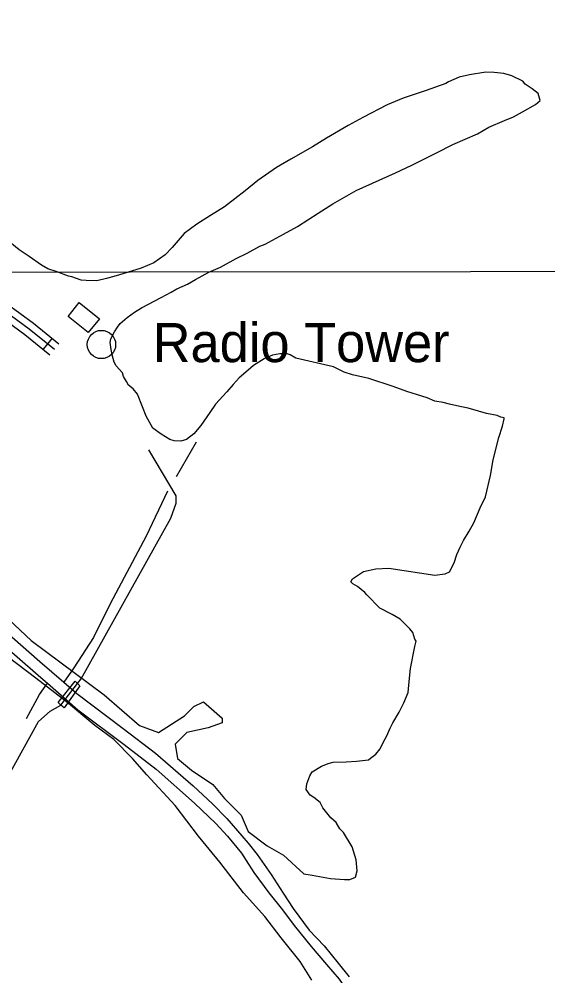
# Model space of a CAD drawing. Extents: x 3297735 to 3335592, y 670436 to 695807.
# Drawn here: x 3318525 to 3319645, y 677364 to 679392 of the extents above; entities that cross this region are included whole.
import ezdxf

# ---------------------------------------------------------------- set-up
doc = ezdxf.new("R2010")
doc.units = 0
for name, color, linetype in [('V-BLDG-OTLN', 7, 'Continuous'), ('V-BRDG-OTLN', 7, 'Continuous'), ('V-DTCH-CNTR', 7, 'Continuous'), ('V-GRID-MAJR', 7, 'Continuous'), ('V-ROAD-CNTR', 7, 'Continuous'), ('V-SITE-VEGE', 7, 'Continuous'), ('V-TOPO-SHOR', 7, 'Continuous'), ('V-TOPO-TOWR', 7, 'Continuous'), ('V-TOPO-TOWR-IDEN', 7, 'Continuous')]:
    doc.layers.add(name, color=color, linetype=linetype)

msp = doc.modelspace()

# ---------------------------------------------------------------- linework, layer by layer
at = {"layer": 'V-BLDG-OTLN'}
msp.add_lwpolyline([(3318652.3, 678791.7), (3318695, 678757.3), (3318671.4, 678728), (3318628.7, 678762.4)], close=True, dxfattribs=at)
at = {"layer": 'V-BRDG-OTLN'}
msp.add_lwpolyline([(3318607.4, 677943.8), (3318643.8, 677989.1), (3318648.7, 677984), (3318653.3, 677979.3), (3318620.4, 677932.6), (3318613.7, 677938.4)], close=True, dxfattribs=at)
at = {"layer": 'V-DTCH-CNTR'}
msp.add_lwpolyline([(3317457.5, 675830.8), (3317578.4, 676057.1), (3317642.4, 676178), (3317859.6, 676585.3), (3318115.7, 677073.2), (3318362.6, 677536.5), (3318566, 677903.4), (3318590.9, 677925.7), (3318613.7, 677938.4), (3318622.6, 677950.1), (3318648.7, 677984), (3318656.8, 677994.1), (3318846.3, 678334.9), (3318857.9, 678366.3), (3318858, 678382), (3318799.5, 678479.6)], dxfattribs=at)
at = {"layer": 'V-GRID-MAJR'}
msp.add_lwpolyline([(3301860.2, 678842.7), (3303311.9, 678843.6), (3306791, 678845.9), (3310174.4, 678848.5), (3313813, 678851.6), (3318760.4, 678856.5), (3322367.1, 678860.5), (3326388.7, 678865.3), (3330442.3, 678870.6), (3332389.2, 678873.4), (3333397.1, 678874.8)], dxfattribs=at)
at = {"layer": 'V-ROAD-CNTR'}
msp.add_line((3318595, 678715.9), (3318576.1, 678692.5), dxfattribs=at)
for points in [[(3317349.6, 679502), (3317551.8, 679371.6), (3317787.2, 679224.3), (3318042.2, 679069), (3318228, 678955.6), (3318331.5, 678889.1), (3318430.2, 678820.7), (3318546.4, 678735.8), (3318599.9, 678692.6)], [(3317357.3, 679514.9), (3317559.8, 679384.3), (3317795, 679237.1), (3318050, 679081.8), (3318236, 678968.3), (3318339.8, 678901.6), (3318438.9, 678832.9), (3318555.6, 678747.7), (3318609.3, 678704.3)], [(3317341.9, 679489.1), (3317543.7, 679358.9), (3317779.3, 679211.5), (3318034.4, 679056.1), (3318220, 678942.9), (3318323.1, 678876.6), (3318421.5, 678808.5), (3318537.3, 678724), (3318590.4, 678680.9)]]:
    msp.add_lwpolyline(points, dxfattribs=at)
at = {"layer": 'V-SITE-VEGE'}
for p, q in [((3319513.7, 679279.7), (3319479.4, 679274.5)), ((3319531.4, 679279.5), (3319513.7, 679279.7)), ((3319552.4, 679277.1), (3319531.4, 679279.5)), ((3319568.9, 679272.6), (3319552.4, 679277.1)), ((3319429.4, 679256.1), (3319407.3, 679248.6)), ((3319435, 679259.4), (3319429.4, 679256.1)), ((3319457.2, 679269.1), (3319435, 679259.4)), ((3319479.4, 679274.5), (3319457.2, 679269.1)), ((3319592, 679261.3), (3319568.9, 679272.6)), ((3319597.5, 679254.6), (3319592, 679261.3)), ((3319611.8, 679244.5), (3319597.5, 679254.6)), ((3319387.3, 679241), (3319338.5, 679224.8)), ((3319407.3, 679248.6), (3319387.3, 679241)), ((3319625, 679234.5), (3319611.8, 679244.5)), ((3319629.3, 679220.1), (3319625, 679234.5)), ((3319338.5, 679224.8), (3319305.2, 679210.8)), ((3319619.2, 679211.3), (3319629.3, 679220.1)), ((3319305.2, 679210.8), (3319253, 679183.6)), ((3319572.6, 679185.2), (3319591.5, 679196.1)), ((3319591.5, 679196.1), (3319619.2, 679211.3)), ((3319253, 679183.6), (3319221.9, 679167.3)), ((3319520.4, 679163.5), (3319553.7, 679177.6)), ((3319553.7, 679177.6), (3319572.6, 679185.2)), ((3319221.9, 679167.3), (3319176.3, 679140)), ((3319496, 679149.4), (3319520.4, 679163.5)), ((3319176.3, 679140), (3319146.3, 679121.5)), ((3319443.8, 679126.6), (3319496, 679149.4)), ((3319146.3, 679121.5), (3319100.7, 679095.3)), ((3319409.4, 679109.2), (3319443.8, 679126.6)), ((3319100.7, 679095.3), (3319070.7, 679077.9)), ((3319357.2, 679083.1), (3319409.4, 679109.2)), ((3319070.7, 679077.9), (3319030.7, 679050.6)), ((3319322.7, 679066.9), (3319357.2, 679083.1)), ((3319239.5, 679028.9), (3319322.7, 679066.9)), ((3319030.7, 679050.6), (3319004, 679028.8)), ((3319004, 679028.8), (3318960.5, 678994.9)), ((3319189.5, 679000.6), (3319239.5, 679028.9)), ((3318960.5, 678994.9), (3318930.5, 678976.3)), ((3319158.3, 678981), (3319189.5, 679000.6)), ((3318930.5, 678976.3), (3318901.6, 678957.8)), ((3319115, 678952.6), (3319158.3, 678981)), ((3318901.6, 678957.8), (3318874.9, 678938.1)), ((3319085, 678936.3), (3319115, 678952.6)), ((3318874.9, 678938.1), (3318849.2, 678908.5)), ((3319046.1, 678915.6), (3319085, 678936.3)), ((3318525.2, 678903.6), (3318497.8, 678926)), ((3319008.3, 678896), (3319035, 678911.3)), ((3319035, 678911.3), (3319046.1, 678915.6)), ((3318546.1, 678889), (3318525.2, 678903.6)), ((3318834.7, 678893.1), (3318810.2, 678875.7)), ((3318849.2, 678908.5), (3318834.7, 678893.1)), ((3318985, 678885.2), (3319008.3, 678896)), ((3318572.5, 678871.1), (3318546.1, 678889)), ((3318585.7, 678863.3), (3318572.5, 678871.1)), ((3318810.2, 678875.7), (3318783.6, 678864.8)), ((3318951.7, 678866.7), (3318985, 678885.2)), ((3318603.3, 678857.6), (3318585.7, 678863.3)), ((3318629.7, 678847.4), (3318603.3, 678857.6)), ((3318735.9, 678849.8), (3318710.4, 678842.3)), ((3318783.6, 678864.8), (3318735.9, 678849.8)), ((3318898.4, 678840.6), (3318927.3, 678855.8)), ((3318927.3, 678855.8), (3318951.7, 678866.7)), ((3318636.4, 678846.2), (3318629.7, 678847.4)), ((3318656.2, 678839.4), (3318636.4, 678846.2)), ((3318667.3, 678838.2), (3318656.2, 678839.4)), ((3318689.4, 678838), (3318667.3, 678838.2)), ((3318710.4, 678842.3), (3318689.4, 678838)), ((3318859.5, 678821), (3318881.7, 678830.8)), ((3318881.7, 678830.8), (3318898.4, 678840.6)), ((3318826.2, 678802.5), (3318847.3, 678813.4)), ((3318847.3, 678813.4), (3318859.5, 678821)), ((3318784, 678780.8), (3318826.2, 678802.5)), ((3318753.9, 678760.1), (3318769.5, 678771)), ((3318769.5, 678771), (3318784, 678780.8)), ((3318739.4, 678746.9), (3318753.9, 678760.1)), ((3318719.2, 678715), (3318727.1, 678729.3)), ((3318727.1, 678729.3), (3318733.8, 678739.2)), ((3318733.8, 678739.2), (3318739.4, 678746.9)), ((3318718.1, 678707.3), (3318719.2, 678715)), ((3318720.1, 678691.8), (3318718.1, 678707.3)), ((3318722.3, 678680.7), (3318720.1, 678691.8)), ((3318726.5, 678665.2), (3318722.3, 678680.7)), ((3319043.9, 678672.4), (3319021.7, 678658.2)), ((3319061.7, 678679.9), (3319043.9, 678672.4)), ((3319077.2, 678683.1), (3319061.7, 678679.9)), ((3319092.7, 678683), (3319077.2, 678683.1)), ((3319099.3, 678680.7), (3319092.7, 678683)), ((3319111.4, 678674), (3319099.3, 678680.7)), ((3319190.9, 678655.6), (3319111.4, 678674)), ((3318730.9, 678657.4), (3318726.5, 678665.2)), ((3318744, 678642.9), (3318730.9, 678657.4)), ((3319010.6, 678648.3), (3318991.6, 678631.9)), ((3319021.7, 678658.2), (3319010.6, 678648.3)), ((3319214, 678644.3), (3319190.9, 678655.6)), ((3318746.2, 678635.2), (3318744, 678642.9)), ((3318752.7, 678624.1), (3318746.2, 678635.2)), ((3318991.6, 678631.9), (3318978.2, 678617.7)), ((3319231.6, 678638.6), (3319214, 678644.3)), ((3319265.8, 678630.6), (3319231.6, 678638.6)), ((3319317.6, 678613.6), (3319265.8, 678630.6)), ((3318757.1, 678616.3), (3318752.7, 678624.1)), ((3318767, 678608.5), (3318757.1, 678616.3)), ((3318775.7, 678597.3), (3318767, 678608.5)), ((3318978.2, 678617.7), (3318964.8, 678602.3)), ((3319346.3, 678603.4), (3319317.6, 678613.6)), ((3318786.5, 678570.7), (3318775.7, 678597.3)), ((3318964.8, 678602.3), (3318941.4, 678576)), ((3319389.3, 678589.7), (3319346.3, 678603.4)), ((3319405.8, 678582.9), (3319389.3, 678589.7)), ((3318794.1, 678550.7), (3318786.5, 678570.7)), ((3318941.4, 678576), (3318929.1, 678558.4)), ((3319423.5, 678579.5), (3319405.8, 678582.9)), ((3319436.7, 678576), (3319423.5, 678579.5)), ((3319458.8, 678571.4), (3319436.7, 678576)), ((3319476.5, 678567.9), (3319458.8, 678571.4)), ((3319498.5, 678561.1), (3319476.5, 678567.9)), ((3318808.2, 678525.2), (3318794.1, 678550.7)), ((3318929.1, 678558.4), (3318910, 678530.9)), ((3319515.1, 678556.5), (3319498.5, 678561.1)), ((3319538.2, 678551.9), (3319515.1, 678556.5)), ((3319546, 678548.5), (3319538.2, 678551.9)), ((3319552.6, 678547.4), (3319546, 678548.5)), ((3319549.1, 678529.7), (3319552.6, 678545.2)), ((3319552.6, 678545.2), (3319552.6, 678547.4)), ((3318825.8, 678512.9), (3318808.2, 678525.2)), ((3318910, 678530.9), (3318895.5, 678513.3)), ((3319541.2, 678505.5), (3319549.1, 678529.7)), ((3318844.5, 678501.6), (3318825.8, 678512.9)), ((3318895.5, 678513.3), (3318879.9, 678501.3)), ((3319529.7, 678458), (3319541.2, 678505.5)), ((3318853.3, 678498.2), (3318844.5, 678501.6)), ((3318867.7, 678498.1), (3318853.3, 678498.2)), ((3318879.9, 678501.3), (3318867.7, 678498.1)), ((3319523.9, 678424.9), (3319529.7, 678458)), ((3319513.5, 678379.6), (3319523.9, 678424.9)), ((3319502.2, 678356.5), (3319513.5, 678379.6)), ((3319488.7, 678324.6), (3319502.2, 678356.5)), ((3319478.6, 678307), (3319488.7, 678324.6)), ((3319466.3, 678287.2), (3319478.6, 678307)), ((3319459.5, 678272.9), (3319466.3, 678287.2)), ((3319452.7, 678257.4), (3319459.5, 678272.9)), ((3319447, 678239.8), (3319452.7, 678257.4)), ((3319231.1, 678206.3), (3319254.5, 678221.6)), ((3319254.5, 678221.6), (3319281.1, 678226.9)), ((3319281.1, 678226.9), (3319308.7, 678228.9)), ((3319308.7, 678228.9), (3319405.9, 678213.6)), ((3319428, 678216.8), (3319436.9, 678221.1)), ((3319436.9, 678221.1), (3319447, 678239.8)), ((3319227.8, 678199.7), (3319231.1, 678206.3)), ((3319405.9, 678213.6), (3319428, 678216.8)), ((3319232.1, 678195.3), (3319227.8, 678199.7)), ((3319242, 678189.6), (3319232.1, 678195.3)), ((3319257.4, 678177.3), (3319242, 678189.6)), ((3319261.8, 678171.8), (3319257.4, 678177.3)), ((3319289.2, 678143.9), (3319261.8, 678171.8)), ((3318475.3, 678145.5), (3318550.3, 678075.5)), ((3319315.6, 678130.4), (3319289.2, 678143.9)), ((3319332.1, 678120.3), (3319315.6, 678130.4)), ((3319352.9, 678100.2), (3319332.1, 678120.3)), ((3319359.5, 678092.4), (3319352.9, 678100.2)), ((3319363.8, 678078), (3319359.5, 678092.4)), ((3318550.3, 678075.5), (3318705.4, 677960.4)), ((3319354.4, 678016.2), (3319363.7, 678062.5)), ((3319363.7, 678062.5), (3319366, 678073.6)), ((3319366, 678073.6), (3319363.8, 678078)), ((3318560.3, 677995.4), (3318480.3, 678055.5)), ((3319352, 677995.2), (3319354.4, 678016.2)), ((3318625.3, 677945.4), (3318560.3, 677995.4)), ((3319349.5, 677965.3), (3319352, 677995.2)), ((3318705.4, 677960.4), (3318780.4, 677895.4)), ((3319340.5, 677943.3), (3319349.5, 677965.3)), ((3318685.4, 677895.4), (3318625.3, 677945.4)), ((3318895.4, 677935.4), (3318915.4, 677945.4)), ((3318915.4, 677945.4), (3318955.4, 677910.4)), ((3319330.4, 677923.5), (3319340.5, 677943.3)), ((3318875.4, 677915.4), (3318895.4, 677935.4)), ((3319316.9, 677900.4), (3319330.4, 677923.5)), ((3318820.4, 677880.3), (3318875.4, 677915.4)), ((3318955.4, 677900.4), (3318925.4, 677890.3)), ((3318955.4, 677910.4), (3318955.4, 677900.4)), ((3319311.3, 677889.4), (3319316.9, 677900.4)), ((3318725.4, 677865.3), (3318685.4, 677895.4)), ((3318780.4, 677895.4), (3318820.4, 677880.3)), ((3318880.4, 677880.3), (3318855.4, 677855.3)), ((3318925.4, 677890.3), (3318880.4, 677880.3)), ((3319303.4, 677871.8), (3319311.3, 677889.4)), ((3318765.4, 677825.3), (3318725.4, 677865.3)), ((3318855.4, 677855.3), (3318860.4, 677825.3)), ((3319289.9, 677845.3), (3319297.8, 677861.9)), ((3319297.8, 677861.9), (3319303.4, 677871.8)), ((3319280.9, 677834.4), (3319289.9, 677845.3)), ((3318795.4, 677790.3), (3318765.4, 677825.3)), ((3318860.4, 677825.3), (3318890.4, 677800.3)), ((3319180.1, 677814.3), (3319190.1, 677817.5)), ((3319190.1, 677817.5), (3319217.8, 677818.3)), ((3319217.8, 677818.3), (3319239.9, 677819.3)), ((3319239.9, 677819.3), (3319265.3, 677822.3)), ((3319265.3, 677822.3), (3319269.8, 677825.6)), ((3319269.8, 677825.6), (3319280.9, 677834.4)), ((3318890.4, 677800.3), (3318935.4, 677770.3)), ((3319141.2, 677788.1), (3319145.7, 677796.9)), ((3319145.7, 677796.9), (3319165.7, 677808.8)), ((3319165.7, 677808.8), (3319171.3, 677811)), ((3319171.3, 677811), (3319180.1, 677814.3)), ((3318855.4, 677725.2), (3318795.4, 677790.3)), ((3319134.4, 677771.5), (3319141.2, 677788.1)), ((3318935.4, 677770.3), (3318960.4, 677740.2)), ((3319133.2, 677759.4), (3319134.4, 677771.5)), ((3319142, 677747.1), (3319133.2, 677759.4)), ((3318960.4, 677740.2), (3318995.4, 677705.2)), ((3319149.7, 677742.6), (3319142, 677747.1)), ((3319162.8, 677731.5), (3319149.7, 677742.6)), ((3318905.4, 677660.2), (3318855.4, 677725.2)), ((3319168.3, 677720.4), (3319162.8, 677731.5)), ((3319185.8, 677699.2), (3319168.3, 677720.4)), ((3318995.4, 677705.2), (3319010.4, 677670.2)), ((3319196.7, 677689.2), (3319185.8, 677699.2)), ((3319204.3, 677675.8), (3319196.7, 677689.2)), ((3319212, 677668), (3319204.3, 677675.8)), ((3318950.4, 677605.1), (3318905.4, 677660.2)), ((3319010.4, 677670.2), (3319050.4, 677640.2)), ((3319230.6, 677638), (3319212, 677668)), ((3319050.4, 677640.2), (3319085.4, 677620.1)), ((3319239.2, 677610.3), (3319230.6, 677638)), ((3319085.4, 677620.1), (3319128.3, 677580.3)), ((3319000.4, 677540.1), (3318950.4, 677605.1)), ((3319241.2, 677587), (3319239.2, 677610.3)), ((3319128.3, 677580.3), (3319146, 677577.9)), ((3319146, 677577.9), (3319169.2, 677573.3)), ((3319169.2, 677573.3), (3319184.6, 677571)), ((3319225.5, 677568.4), (3319237.7, 677573.8)), ((3319237.7, 677573.8), (3319241.2, 677587)), ((3319184.6, 677571), (3319214.5, 677568.5)), ((3319214.5, 677568.5), (3319225.5, 677568.4)), ((3319045.4, 677490.1), (3319000.4, 677540.1)), ((3319080.4, 677445), (3319045.4, 677490.1)), ((3319120.4, 677395), (3319080.4, 677445)), ((3319145.4, 677355), (3319120.4, 677395))]:
    msp.add_line(p, q, dxfattribs=at)
at = {"layer": 'V-TOPO-SHOR'}
msp.add_line((3318900.1, 678495.5), (3318858, 678421.9), dxfattribs=at)
for points in [[(3318053.7, 678460.2), (3318115.9, 678406.7), (3318250.6, 678295.9), (3318319.7, 678242.7), (3318450.8, 678133.6), (3318568.6, 678030.9), (3318619.4, 677986.9)], [(3318839.5, 678392), (3318794.4, 678296.7), (3318717.6, 678153), (3318682.5, 678081.3), (3318641.2, 678017.6), (3318619.4, 677986.9)], [(3318304.5, 678224.7), (3318325.7, 678209.4), (3318452.9, 678099.6), (3318570.7, 677996.9), (3318584.8, 677984.6)], [(3318540.5, 677909.7), (3318567.9, 677960.9), (3318584.8, 677984.6)], [(3318584.8, 677984.6), (3318649.6, 677928.6), (3318747.4, 677854.9), (3318815.7, 677802.5), (3318896.6, 677730.2), (3318941.7, 677687.5), (3318966.7, 677660.8), (3318996.5, 677624.2), (3319005.8, 677609), (3319022.2, 677583.6), (3319053.9, 677540.6), (3319082.8, 677504), (3319107.8, 677470.9), (3319143.8, 677426.7), (3319176.3, 677388.1), (3319203.3, 677357), (3319217.4, 677337.1), (3319238.5, 677311.6), (3319247.3, 677300)], [(3318619.4, 677986.9), (3318647.5, 677962.6), (3318745.3, 677889), (3318813.7, 677836.6), (3318894.1, 677767.4), (3318934.9, 677729.1), (3318965.1, 677697.6), (3318997.2, 677660.9), (3319010.5, 677645.8), (3319029.7, 677621.5), (3319059, 677579.3), (3319084.3, 677539.5), (3319105.8, 677506.9), (3319139.4, 677461.5), (3319171.5, 677428), (3319200.9, 677391.4), (3319224.4, 677362.3)]]:
    msp.add_lwpolyline(points, dxfattribs=at)
at = {"layer": 'V-TOPO-TOWR'}
msp.add_line((3318699.5, 678702.7), (3318699.5, 678702.7), dxfattribs=at)
msp.add_circle((3318699.5, 678702.7), 30, dxfattribs=at)

# ---------------------------------------------------------------- texts
at = {"layer": 'V-TOPO-TOWR-IDEN'}
msp.add_text('Radio Tower', height=83, dxfattribs=at).set_placement((3318808, 678665.3))

doc.saveas('drawing.dxf')
